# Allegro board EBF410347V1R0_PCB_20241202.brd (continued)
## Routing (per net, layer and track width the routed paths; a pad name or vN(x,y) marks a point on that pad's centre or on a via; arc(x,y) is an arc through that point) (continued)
VDD_5V: length 56.1
  TOP w0.203: C143.1 U22.6 ; U21.6 C132.1
  TOP w0.254: C143.1 17.14,51.56 16.84,51.26 16.84,47.01 17.25,46.61 C132.1 v1(17.92,47.34)
  TOP w0.381: R259.1 v1(124.08,15.52)
  BOTTOM w0.254: v1(11.18,54.81) 11.18,60.15 10.87,60.45 7.95,60.45 7.68,60.72 7.68,62.28 R1.2 C2.2
  BOTTOM w0.381: R84.1 26.92,23.98 27.36,24.41 v1(29.71,24.41) ; R169.1 9.26,66.22 9.66,65.83 v1(10.51,65.83) ; R132.1 v1(123.97,49.15) ; v1(122.55,31.01) C158.1 122.55,28.07 122.29,27.81 U18.3 ; R170.1 9.92,59.56 10.18,59.31 v1(10.18,54.81) ; v1(125.48,42.53) 125.05,42.95 122.89,42.95 122.55,42.61 C161.1 122.55,38.86 122.29,38.61 U19.3 ; R21.1 24.68,40.38 v1(24.68,41.43)
  vias: v1(10.18,53.81) v1(10.18,52.81) v1(10.36,37.79) v1(10.36,36.79) v1(10.36,26.29) v1(10.36,25.29) v1(11.18,53.81) v1(11.18,52.81) v1(11.34,20.32) v1(12.34,20.32) v1(16.51,42.16) v1(16.51,40.97) v1(125.08,15.52)
VDD_LCD_3V3: length 18.9
  TOP w0.254: v1(15.53,23) 15.48,23.05 U14.1 ; v1(78.71,19.42) 78.17,18.89 74.69,18.89 v1(74.15,19.42) 73.62,18.89 68.65,18.89 68.28,18.52 68.28,16.74 67.77,16.23 v1(67.03,16.23)
  BOTTOM w0.254: R176.1 v1(78.71,19.42) ; C140.1 C139.1 15.51,22.99 v1(15.53,23) ; R177.1 v1(74.15,19.42)
  vias: v1(15.53,24) v1(66.03,16.23)
VDD_LCD_5V:
  vias: v1(17.72,13.27) v1(18.72,13.27) v1(67.03,15.23) v1(67.03,14.23)
VDD_LVDS: length 24.9
  TOP w0.254: Y2.4 v1(18.16,32.98)
  TOP w0.381: U27.5 v1(12.99,26.61) ; v1(16.54,27.55) 16.76,27.33 16.76,22.45 17.52,21.7
  ART03 w0.254: v1(18.16,32.98) 17.26,32.08 13.31,32.08 12.8,31.57 12.8,29.36 12.52,29.08 12.52,27.08 v1(12.99,26.61)
  ART04 w0.381: v1(12.99,26.61) 13.67,25.93 16.26,25.93 16.54,26.22 v1(16.54,27.55)
VDDIO_LVDS: length 17.2
  TOP w0.203: U10.10 29.44,27.91
  TOP w0.254: v1(32.89,30.22) 32.89,32.35 32.53,32.71 31.71,32.71 C113.1 ; C93.1 v1(30.4,27.05) 30.4,27.64 30.13,27.91 29.44,27.91
  TOP w0.381: v1(29.4,30.1) 30.42,31.11 C94.1 C113.1 30.82,32.43 L13.2
  BOTTOM w0.254: C93.1 v1(30.4,27.05) 29.67,27.05 29.41,27.31 C91.1 C112.1 29.41,30.1 v1(29.4,30.1) ; R73.1 v1(32.89,30.22)
BAT_RTC: length 10.1
  TOP w0.381: J23.1 122.89,61.11 122.48,60.7 D44.2 117.93,60.03 C116.1 v1(118.7,59.31)
  BOTTOM w0.381: v1(118.7,59.31) 118.76,59.37 D43.1
BT_HOST_WAKE: length 52.3
  TOP w0.173: R158.1 v1(108.54,72.62) ; J3.46 82.34,63.9 82.02,63.58 82.02,61.82 81,60.81 v1(77.42,60.81)
  ART03 w0.16: v1(108.54,72.62) 107.83,73.33 99.46,73.33 98.93,72.81 98.93,68.55 98.53,68.15 93.2,68.15 91.52,66.47 77.49,66.47 77.17,66.15 77.17,61.06 v1(77.42,60.81)
BT_REG_ON: length 44.9
  TOP w0.173: v1(85.84,63.9) 85.8,63.93 85.8,64.59 85.59,64.8 J3.47 ; v1(117.7,55.89) 118.7,55.89 119.19,56.39 119.19,57.55 118.82,57.91 R155.2
  BOTTOM w0.173: v1(85.84,63.9) 86.03,63.71 86.03,60.67 86.38,60.32 96.89,60.32 97.65,59.56 99.29,59.56 99.85,59 99.85,57.09 100.19,56.74 116.85,56.74 v1(117.7,55.89)
BT_UART_CTS: length 2.4
  TOP w0.173: R154.2 116.67,65.91 U16.44
BT_UART_RTS: length 3.3
  TOP w0.173: U16.41 116.84,63.21 R150.2 R129.1
BT_UART_RXD: length 2.3
  TOP w0.173: R153.2 116.78,65 U16.43
BT_UART_TXD: length 2.3
  TOP w0.173: U16.42 116.9,64.11 R152.2
BT_WAKE: length 55.3
  TOP w0.173: v1(77.42,59.81) 78.01,60.4 81.1,60.4 82.7,62 82.7,62.71 82.99,63 J3.45
  TOP w0.254: R156.1 v1(109.55,72.62)
  ART03 w0.254: v1(109.55,72.62) 108.38,73.79 99.17,73.79 98.45,73.07 98.45,68.92 98.13,68.6 92.61,68.6 91.16,67.16 77.01,67.16 76.5,66.65 76.5,60.72 v1(77.42,59.81)
CAM0_NRST: length 50.6
  TOP w0.173: v1(30.51,39.6) 29.69,40.43 U17.5
  ART03 w0.16: v1(30.51,39.6) 29.91,38.99 24.17,38.99 23.85,38.67 23.85,36.82 23.38,36.35 16.48,36.35 15.28,35.14 12.06,35.14 11.79,34.87 11.79,29.18 11.43,28.83 11.43,21.08 5.97,15.62 5.97,12.95 v1(5.37,12.36)
  BOTTOM w0.173: J24.22 v1(5.37,12.36)
CAM0_PWDN: length 47.5
  TOP w0.173: v1(29.51,39.6) 29.34,39.78 U17.4
  ART03 w0.16: v1(5.37,14.86) 5.37,15.62 10.97,21.22 10.97,29.01 10.69,29.29 10.69,30.1 11.33,30.73 11.33,35.03 11.86,35.56 14.99,35.56 16.1,36.68 23.02,36.68 23.34,37 23.34,39.28 23.66,39.6 v1(29.51,39.6)
  BOTTOM w0.173: v1(5.37,14.86) 5.38,14.87 5.38,15.57 5.67,15.86 J24.15
CAM1_NRST: length 39.4
  TOP w0.173: v1(25.43,44.96) 25.43,43.93 26.19,43.18 26.19,42.06 26.52,41.73 U17.7
  ART03 w0.16: v1(5.38,29.75) 6.23,30.6 6.23,36.87 7.24,37.88 7.24,42.52 7.56,42.84 19.4,42.84 21.01,44.45 24.93,44.45 v1(25.43,44.96)
  BOTTOM w0.173: J28.22 v1(5.38,29.75)
CAM1_PWDN: length 36.9
  TOP w0.173: U17.6 25.54,41.08 25.19,41.42 25.19,43.36 24.43,44.12 v1(24.43,44.96)
  ART03 w0.16: v1(24.43,44.96) 21.03,44.96 19.23,43.15 7.25,43.15 6.93,42.83 6.93,38.01 5.92,37 5.92,33.79 v1(5.38,33.25)
  BOTTOM w0.173: J28.15 v1(5.38,33.25)
CAM2_NRST: length 34.2
  TOP w0.173: U17.9 29.18,43.03 29.46,43.31 v1(29.46,44.5)
  BOTTOM w0.173: J29.22 7.47,47.15 7.77,47.45 7.77,50.32 8.21,50.75 15.5,50.75 16.21,51.46 18.61,51.46 19.76,50.32 19.76,48.36 21.01,47.12 29.11,47.12 29.46,46.76 v1(29.46,44.5)
CAM2_PWDN: length 34.3
  TOP w0.173: v1(30.46,44.5) 30.46,42.71 30.13,42.38 U17.8
  BOTTOM w0.173: J29.15 7.59,50.65 8.03,51.08 15.27,51.08 15.98,51.79 18.89,51.79 20.24,50.43 20.24,48.39 21.01,47.62 30.12,47.62 30.46,47.28 v1(30.46,44.5)
CAM3_NRST: length 49.4
  TOP w0.173: v1(24.68,51.69) 24.68,51.21 24.91,50.98 25.98,50.98 26.39,50.57 26.39,44.6 26.67,44.33 U17.11
  ART03 w0.16: v1(24.68,51.69) 24.2,52.17 24.2,57.46 23.88,57.78 6.71,57.78 6.36,58.13 6.36,62.32 5.93,62.74 1.82,62.74 v1(1.78,62.78)
  BOTTOM w0.173: J30.22 5.56,64.51 5.36,64.31 5.36,63.65 5.05,63.35 2.35,63.35 v1(1.78,62.78)
CAM3_PWDN: length 54.6
  TOP w0.173: v1(23.68,51.69) 23.67,51.68 23.67,50.85 23.95,50.57 25.64,50.57 25.98,50.22 25.98,44.14 26.45,43.68 U17.10
  ART03 w0.16: v1(1.78,63.78) 1.27,63.27 1.27,62.56 1.56,62.27 5.65,62.27 5.97,61.94 5.97,57.85 6.42,57.4 23.36,57.4 23.72,57.04 23.72,51.73 v1(23.68,51.69)
  BOTTOM w0.173: v1(1.78,63.78) 4.53,63.78 4.9,64.15 4.9,67.67 5.25,68.01 J30.15
CAN0_H: length 3.2
  BOTTOM w0.173: R238.1 R237.1 127.63,26.54 U18.7
CAN0_L: length 3.2
  BOTTOM w0.173: R251.1 R237.2 127.63,27.81 U18.6
CAN0_RX_M2: length 1.2
  BOTTOM w0.173: R243.2 R240.1
CAN0_TX_M2: length 1.2
  BOTTOM w0.173: R241.2 R239.1
CAN1_H: length 3.2
  BOTTOM w0.173: U19.7 127.63,37.34 R247.1 R252.1
CAN1_L: length 3.2
  BOTTOM w0.173: R258.1 R247.2 127.63,38.61 U19.6
CAN1_RX_M1: length 1
  BOTTOM w0.173: R257.2 R246.1
CAN1_TX_M1: length 1
  BOTTOM w0.173: R245.1 R248.2
CLK_32K_IN: length 93.9
  TOP w0.173: v1(82.04,57.48) 81.99,57.43 81.99,24 82.09,23.9 J3.200
  ART03 w0.16: v1(82.04,57.48) 83.26,57.48 83.57,57.78 83.57,59.69 83.93,60.06 93.79,60.06 95.33,61.59 100.15,61.59 100.56,62 100.56,64.41 100.84,64.69 105.66,64.69 106.07,64.29 106.07,61.95 106.4,61.62 120.21,61.62 v1(120.7,62.1)
  BOTTOM w0.173: R135.2 118.48,65.63 118.49,65.64 120.18,65.64 120.7,65.13 v1(120.7,62.1)
DGB_RX: length 5.5
  TOP w0.173: J15.2 4.1,82.57 D30.1 4.1,79.02 R70.1
DGB_TX: length 5.6
  TOP w0.173: R69.1 8.29,79.02 D31.1 8.29,82.36 J15.1
ETH_PHY_LED1: length 76.5
  TOP w0.173: v1(50.39,40.67) 49.69,39.97 J3.164
  ART03 w0.16: J10.10 26.59,71.97 26.91,71.65 36.83,71.65 38.48,70 47.73,70 48.13,69.59 48.13,59.63 50.29,57.47 50.29,40.77 v1(50.39,40.67)
ETH_PHY_LED2: length 66.4
  TOP w0.173: J3.165 50.59,39.41 51.39,40.21 v1(51.39,40.67)
  ART03 w0.16: J10.12 38.42,70.78 38.84,70.36 48.22,70.36 48.54,70.04 48.54,59.92 50.77,57.68 50.77,41.29 v1(51.39,40.67)
ETH_PHY_MDIN0: length 54.6
  TOP w0.114: J3.153 39.79,22.35 39.46,22.68 39.46,25.63 39.79,25.96 42.09,25.96 42.6,26.47 42.6,51.08 42.82,51.31 v1(42.98,51.31)
  BOTTOM w0.114: v1(42.98,51.31) 42.66,51.63 42.66,52.42 42.18,52.9 39.2,52.9 38.5,52.2 34.29,52.2 34.06,52.42 34.06,56.11 33.71,56.46 29.34,56.46 28.95,56.85 28.95,58.47 C55.1
ETH_PHY_MDIN1: length 51.6
  TOP w0.114: v1(44.71,52.98) 44.39,52.66 44.39,25.21 44.06,24.88 42.39,24.88 42.16,24.65 42.16,22.68 42.49,22.35 J3.156
  BOTTOM w0.114: v1(44.71,52.98) 44.39,53.31 44.39,53.99 43.98,54.39 39.4,54.39 38.39,53.39 35.7,53.39 35.56,53.53 35.56,57.02 35.2,57.38 33.6,57.38 33.39,57.59 33.39,58.47 C57.1
ETH_PHY_MDIN2: length 46.7
  TOP w0.114: J3.159 45.19,22.35 44.86,22.68 44.86,23.51 45.01,23.66 45.83,23.66 46.09,23.91 46.09,54.33 v1(46.41,54.66)
  BOTTOM w0.114: v1(46.41,54.66) 46.08,55 46.08,55.61 45.71,55.98 38.3,55.98 37.84,56.44 37.84,58.47 C59.1
ETH_PHY_MDIN3: length 42.9
  TOP w0.114: v1(42.61,57.48) 42.28,57.15 42.28,56.44 42.51,56.22 47.19,56.22 47.56,55.85 47.56,22.68 47.89,22.35 J3.162
  BOTTOM w0.114: C61.1 42.28,58.47 42.28,57.8 v1(42.61,57.48)
ETH_PHY_MDIP0: length 54.4
  TOP w0.114: J3.152 38.89,22.35 39.22,22.68 39.22,25.73 39.69,26.2 41.99,26.2 42.35,26.57 42.35,51.05 v1(42.09,51.31)
  BOTTOM w0.114: C54.1 28.71,58.47 28.71,56.75 29.24,56.22 33.61,56.22 33.82,56.01 33.82,52.32 34.19,51.95 38.6,51.95 39.3,52.66 42.08,52.66 42.42,52.32 42.42,51.63 v1(42.09,51.31)
ETH_PHY_MDIP1: length 51.8
  TOP w0.114: v1(43.82,52.98) 43.99,52.98 44.15,52.83 44.15,25.31 43.96,25.12 42.29,25.12 41.92,24.75 41.92,22.68 41.59,22.35 J3.155
  BOTTOM w0.114: v1(43.82,52.98) 43.99,52.98 44.15,53.14 44.15,53.89 43.88,54.15 39.5,54.15 38.49,53.15 35.6,53.15 35.32,53.43 35.32,56.92 35.1,57.14 33.5,57.14 33.15,57.49 33.15,58.47 C56.1
ETH_PHY_MDIP2: length 46.9
  TOP w0.114: J3.158 44.29,22.35 44.62,22.68 44.62,23.61 44.91,23.9 45.73,23.9 45.85,24.01 45.85,54.53 45.72,54.66 v1(45.52,54.66)
  BOTTOM w0.114: v1(45.52,54.66) 45.62,54.66 45.83,54.88 45.83,55.51 45.61,55.74 38.2,55.74 37.6,56.34 37.6,58.47 C58.1
ETH_PHY_MDIP3: length 42.9
  TOP w0.114: v1(41.72,57.48) 42.04,57.15 42.04,56.34 42.41,55.98 47.09,55.98 47.32,55.75 47.32,22.68 46.99,22.35 J3.161
  BOTTOM w0.114: C60.1 42.04,58.47 42.04,57.8 v1(41.72,57.48)
EXT_PWR_EN: length 115
  TOP w0.173: J3.13 v1(85.46,34.2)
  ART03 w0.16: v1(41.63,40.27) 43.9,40.27 44.22,40.59 44.22,67.24 43.9,67.56 31.36,67.56 31.04,67.24 31.04,62.64 30.66,62.25 16.72,62.25 v1(16.15,62.83)
  BOTTOM w0.173: R3.2 17.12,61.86 v1(16.15,62.83) ; v1(41.63,40.27) 45.98,40.27 46.33,39.92 46.33,34.51 46.63,34.21 85.45,34.21 v1(85.46,34.2)
FAN_CTRL: length 60.9
  TOP w0.173: v1(117.91,46.92) 124.55,46.92 124.97,47.34 v1(124.97,49.15) ; J3.40 85.35,58.5 85.7,58.85 85.7,59.54 86.53,60.36 v1(86.53,61.21)
  BOTTOM w0.173: v1(117.91,46.92) 119.06,46.92 119.41,47.27 119.41,54.89 117.14,57.16 100.65,57.16 100.3,57.5 100.3,60.46 99.81,60.96 93.42,60.96 92.93,61.46 86.77,61.46 v1(86.53,61.21) ; R137.1 v1(124.97,49.15)
GM8775C_DA0N: length 6
  TOP w0.114: U10.15 27.15,30.16 27.28,30.29 27.28,31.26 27.56,31.55 28.19,31.55 28.45,31.29 28.45,30.99 28.57,30.86 28.96,30.86 29.08,30.98 29.08,32.06 28.97,32.18 28.82,32.18 28.7,32.29 R89.2
GM8775C_DA0P: length 6
  TOP w0.114: R86.2 29.7,32.29 29.59,32.18 29.44,32.18 29.32,32.06 29.32,30.88 29.06,30.62 28.48,30.62 28.21,30.89 28.21,31.19 28.09,31.3 27.66,31.3 27.52,31.16 27.52,30.29 27.65,30.16 U10.14
GM8775C_DA1N: length 3.7
  TOP w0.114: R93.2 27.08,32.24 27.08,32.06 26.9,31.89 26.56,31.89 26.28,31.61 26.28,30.29 26.15,30.16 U10.17
GM8775C_DA1P: length 3.8
  TOP w0.114: R90.2 27.32,32.23 27.32,31.96 27,31.65 26.66,31.65 26.52,31.51 26.52,30.29 26.65,30.16 U10.16
GM8775C_DA2N: length 4.2
  TOP w0.114: R97.2 22.7,32.29 22.82,32.18 22.97,32.18 23.08,32.06 23.08,31.8 23.44,31.44 24.08,31.44 24.28,31.25 24.28,30.29 24.15,30.16 U10.21
GM8775C_DA2P: length 4.2
  TOP w0.114: U10.20 24.65,30.16 24.52,30.29 24.52,31.35 24.18,31.69 23.54,31.69 23.32,31.9 23.32,32.06 23.44,32.18 23.59,32.18 23.7,32.29 R94.2
GM8775C_DA3N: length 4.9
  TOP w0.114: R102.2 20.7,32.29 20.82,32.18 20.97,32.18 21.08,32.06 21.08,31.59 21.62,31.05 22.75,31.05 23.28,30.52 23.28,30.29 23.15,30.16 U10.23
GM8775C_DA3P: length 4.9
  TOP w0.114: R99.2 21.7,32.29 21.59,32.18 21.44,32.18 21.32,32.06 21.32,31.69 21.72,31.29 22.85,31.29 23.52,30.62 23.52,30.29 23.65,30.16 U10.22
GM8775C_DACN: length 3.3
  TOP w0.114: U10.19 25.15,30.16 25.28,30.29 25.28,31.38 25.08,31.57 25.08,32.24 R107.2
GM8775C_DACP: length 3.3
  TOP w0.114: U10.18 25.65,30.16 25.52,30.29 25.52,31.48 25.32,31.67 25.32,32.24 R104.2
GM8775C_RSTN: length 53.3
  TOP w0.173: C95.1 v1(30.4,30.1) 29.9,29.59 29.9,29.11 29.7,28.91 U10.12
  BOTTOM w0.173: v1(30.4,30.1) 30.53,30.22 R73.2 31.73,29.62 33.56,29.62 33.91,29.27 33.91,27.45 34.25,27.1 69.12,27.1 69.47,26.76 69.47,19.18 R187.2
GPIO0_C0: length 59.8
  TOP w0.173: v1(87.19,59.32) 87.18,59.31 87.18,58.1 85.78,56.7 J3.38
  BOTTOM w0.173: R248.1 118.74,36.43 R253.1 116.84,36.33 116.84,40.64 116.41,41.07 116.41,47.55 117.91,49.05 117.91,53.49 115.45,55.96 99.54,55.96 99.01,56.49 99.01,57.1 98.7,57.4 96.57,57.4 96.22,57.76 96.22,58.98 95.87,59.32 v1(87.19,59.32)
GPIO0_C1: length 56.3
  TOP w0.173: J3.39 85.82,57.6 86.19,57.97 v1(86.19,59.32)
  BOTTOM w0.173: v1(86.19,59.32) 86.69,59.82 96.38,59.82 96.73,59.47 96.73,58.75 97.06,58.42 98.93,58.42 99.39,57.96 99.39,56.77 99.85,56.31 116.56,56.31 118.4,54.48 118.4,47.91 118.08,47.6 117.19,47.6 116.84,47.25 116.84,43.92 117.74,43.02 R255.1 117.74,40.5 R257.1
GPIO0_C6: length 84.8
  TOP w0.173: J3.43 82.66,61.2 v1(82.65,61.19)
  BOTTOM w0.173: R242.1 R241.1 124.17,22.07 119.16,22.07 118.75,22.48 118.75,31.09 118.31,31.52 115.19,31.52 114.25,32.46 114.25,40.11 115.6,41.46 115.6,47.88 116.41,48.69 116.41,51.46 115.49,52.37 110.41,52.37 109.25,53.54 105.66,53.54 104.55,52.42 100.13,52.42 99.49,53.06 96.39,53.06 95.73,53.72 92.22,53.72 91.89,54.05 91.89,54.86 91.54,55.21 83.98,55.21 82.93,56.26 82.93,59.03 82.09,59.87 82.09,60.63 v1(82.65,61.19)
GPIO0_C7: length 72.6
  TOP w0.173: J3.44 85.19,62.1 85.53,61.77 v1(85.53,61.21)
  BOTTOM w0.173: v1(85.53,61.21) 85.53,58.49 85.87,58.14 95.36,58.14 95.71,57.79 95.71,56.68 96.06,56.34 98.5,56.34 99.31,55.52 115.24,55.52 117.53,53.24 117.53,49.22 116.08,47.78 116.08,41.25 114.71,39.88 114.71,33.02 115.17,32.56 123.9,32.56 R243.1 R244.1
GPIO0C0: length 10.5
  BOTTOM w0.173: R253.2 118.74,34.3 119,34.03 127.13,34.03 127.75,33.41 R254.1
GPIO0C1: length 13.4
  BOTTOM w0.173: R255.2 118.36,40.88 118.36,43.18 118.87,43.69 127.38,43.69 127.76,43.31 R256.1
GPIO0C6: length 1
  BOTTOM w0.173: R242.2 126.75,22.61 R249.1
GPIO0C7: length 1
  BOTTOM w0.173: R250.1 126.75,31.74 R244.2
HP_BUTTON_DET: length 109.7
  TOP w0.173: v1(86.5,55.7) 86.1,55.29 86.1,52.5 85.79,52.2 J3.33
  ART03 w0.16: v1(86.5,55.7) 76.24,55.7 75.92,56.02 75.92,62.31 75.55,62.68 75.55,67.47 75.87,67.79 85.7,67.79 86.39,68.48 86.39,71.38 86.71,71.7 94.4,71.7 94.81,72.11 94.81,77.01 96.09,78.29 96.09,81.33 95.38,82.03 76.65,82.03 74.88,80.26 72.14,80.26 71.01,81.39 v1(55.43,81.39)
  BOTTOM w0.173: C40.1 R29.1 ; C40.1 53.25,78.82 54.59,78.82 54.92,79.15 54.92,80.88 v1(55.43,81.39) ; C40.1 R26.2
HP_PLUG_IN_DET: length 86.7
  TOP w0.173: J3.196 v1(78.49,22.71)
  ART03 w0.16: v1(52.45,82.41) 52.45,81.14 52.7,80.88 66.88,80.88 67.49,80.27 67.49,69.7 67.81,69.38 71.65,69.38 72.01,69.02 72.01,23.03 72.33,22.71 v1(78.49,22.71)
  BOTTOM w0.173: R36.2 v1(52.45,82.41)
HP_SNS: length 69.2
  TOP w0.254: J3.22 82.86,42.3 v1(82.86,42.3)
  ART03 w0.254: v1(52.39,41.94) 52.39,58 49.83,60.55 v1(49.83,72.61)
  BOTTOM w0.254: v1(82.86,42.3) 82.59,42.57 53.02,42.57 v1(52.39,41.94) ; v1(49.83,72.61) 49.29,73.15 47.37,73.15 46.61,72.39 45.84,72.39 R38.2
HPL_OUT: length 178.1
  TOP w0.254: J3.21 82.96,41.4 v1(82.86,41.3)
  ART03 w0.254: v1(50.83,72.61) 50.24,72.02 50.24,60.81 52.8,58.25 52.8,42.54 v1(53.39,41.94)
  ART04 w0.254: v1(50.83,72.61) 50.22,73.23 48.51,73.23 48.13,72.85 48.13,70.08 47.75,69.7 18.29,69.7 17.78,70.2 17.78,72.97 17.12,73.63 6.4,73.63 5.89,73.13 5.89,44.17 6.65,43.41 6.65,27.94 7.16,27.43 14.73,27.43 15.84,28.54 v1(15.84,29.84)
  BOTTOM w0.254: C34.1 15.49,30.19 v1(15.84,29.84) ; v1(82.86,41.3) 82,42.16 53.61,42.16 v1(53.39,41.94) ; R33.2 46.79,73.58 49.86,73.58 v1(50.83,72.61)
HPR_OUT: length 141.5
  TOP w0.254: J3.23 82.96,43.2 v1(82.86,43.3)
  ART03 w0.254: v1(51.39,41.94) 51.98,42.54 51.98,57.77 49.43,60.33 49.43,72.02 v1(48.83,72.61)
  ART04 w0.254: v1(9.18,55.81) 7.04,55.81 6.35,56.5 6.35,72.62 6.86,73.13 16.79,73.13 17.3,72.62 17.3,69.62 17.81,69.11 48.33,69.11 48.83,69.62 v1(48.83,72.61)
  BOTTOM w0.254: C46.1 9.18,54.06 v1(9.18,55.81) ; v1(51.39,41.94) 52.43,42.98 82.54,42.98 v1(82.86,43.3) ; R34.2 45.25,71.96 46.86,71.96 47.52,72.61 v1(48.83,72.61)
I2C0_SCL: length 203.1
  TOP w0.173: U17.22 26.03,39.13 26.48,38.68 v1(26.48,36.71) ; J3.194 76.69,23.91 77.03,24.26 80.6,24.26 80.95,24.6 v1(80.95,57.48)
  ART03 w0.16: v1(112.92,62.68) 112.73,62.48 107.08,62.48 106.73,62.83 106.73,64.86 106.41,65.18 100.1,65.18 99.67,64.74 99.67,63.04 99.24,62.61 95.4,62.61 93.33,60.54 91.24,60.54 90.98,60.8 83.38,60.8 83.08,60.5 83.08,58.52 82.66,58.09 81.56,58.09 v1(80.95,57.48)
  BOTTOM w0.173: v1(112.92,62.68) 113.2,62.41 U15.6 ; v1(80.95,57.48) 80.95,56.18 80.59,55.83 50.27,55.83 49.33,54.89 49.33,46.81 49.15,46.63 39.8,46.63 39.01,45.85 33.1,45.85 32.56,45.31 32.56,40.74 30.84,39.01 28.82,39.01 28.19,38.39 28.19,37.06 27.85,36.71 v1(26.48,36.71) 25.95,37.24 25.3,37.24 24.33,36.27 23.44,36.27 23.21,36.03 23.21,35.11 23.04,34.94 16.44,34.94 15.88,35.51 9.03,35.51 8.69,35.16 8.69,29.66 5,25.98 1.91,25.98 1.47,25.54 1.47,21.2 1.65,21.03 2.84,21.03 3.52,20.36 J24.6
I2C0_SDA: length 205.6
  TOP w0.173: J3.193 75.79,24.42 76.13,24.76 79.97,24.76 80,24.81 80.37,25.18 80.37,58.03 v1(80.95,58.61) ; U17.23 25.13,38.48 25.48,38.13 v1(25.48,36.71)
  ART03 w0.16: v1(80.95,58.61) 80.26,59.29 80.26,63.1 80.58,63.42 92.13,63.42 93.98,65.28 95.63,65.28 96.77,66.42 106.89,66.42 107.21,66.1 107.21,64.18 107.72,63.68 v1(112.92,63.68)
  BOTTOM w0.173: U15.5 113.24,63.06 112.92,63.38 v1(112.92,63.68) ; J24.5 3.52,20.86 2.95,21.44 2.06,21.44 1.87,21.63 1.87,25.31 2.22,25.65 5.33,25.65 9.14,29.46 9.14,34.84 9.49,35.18 15.69,35.18 16.26,34.61 24.04,34.61 24.21,34.79 24.21,35.77 24.38,35.94 24.7,35.94 v1(25.48,36.71) 26.12,36.07 28.36,36.07 28.7,36.41 28.7,38.2 29.18,38.68 31.09,38.68 32.97,40.56 32.97,44.88 33.48,45.39 39.07,45.39 39.83,46.15 49.67,46.15 49.89,46.37 49.89,54.76 50.47,55.35 80.95,55.35 81.44,55.83 81.44,58.11 v1(80.95,58.61)
I2C1_SCL_M1: length 182.1
  TOP w0.173: v1(66.93,18.42) 65.53,17.02 65.53,12.24 65.16,11.86 63.17,11.86 v1(62.68,12.36) 62.06,12.36 60.55,13.87 48.83,13.87 48.49,14.22 48.49,18.45 48.14,18.79 32.47,18.79 32.12,19.14 R74.1 32.89,23.76 v1(32.89,24) ; J3.57 76.69,65.63 76.34,65.28 v1(69.39,65.28) ; v1(4.36,38.75) 4.36,35.76 3.89,35.28 3.89,27.91 4.27,27.53 4.27,23.21 3.89,22.83 v1(3.89,22.36) 3.89,18.64 4.23,18.29 J19.4
  ART03 w0.16: v1(69.39,65.28) 69.39,18.74 69.07,18.42 v1(66.93,18.42)
  BOTTOM w0.173: v1(69.39,65.28) 69.34,65.24 R174.2 ; J18.9 62.18,12.86 v1(62.68,12.36) ; v1(4.36,38.75) 4.36,38.1 4.71,37.75 J28.6 ; v1(3.89,22.36) 4.39,21.85 5.34,21.85 5.66,22.17 5.66,24.71 9.96,29.01 13.51,29.01 13.87,28.65 18.85,28.65 19.2,29.01 26.67,29.01 27.13,28.54 27.13,26.31 27.48,25.96 30.07,25.96 30.48,25.55 30.48,24.26 30.73,24 v1(32.89,24)
I2C1_SDA_M1: length 180
  TOP w0.173: R75.1 32.89,24.77 v1(32.89,25) 33.39,24.51 33.39,19.6 33.73,19.25 48.55,19.25 48.9,18.91 48.9,14.54 49.24,14.2 60.78,14.2 62.13,12.85 63.19,12.85 v1(63.68,12.36) 64.83,12.36 65.18,12.7 65.18,17.67 v1(66.93,19.42) ; v1(4.36,39.75) 4.77,39.75 5.16,39.37 5.16,35.53 4.62,35 4.62,28.37 4.89,28.11 v1(4.89,22.36) 4.89,20.7 5.3,20.29 J19.5 ; J3.58 75.79,66.13 75.44,65.79 68.88,65.79 v1(68.37,65.28)
  ART03 w0.16: v1(66.93,19.42) 68.64,19.42 68.96,19.74 68.96,64.69 v1(68.37,65.28)
  BOTTOM w0.173: v1(63.68,12.36) 63.18,11.86 62.43,11.86 61.68,12.62 J18.10 ; J28.5 5.19,38.25 4.89,38.55 4.89,39.22 v1(4.36,39.75) ; v1(32.89,25) 31.13,25 30.86,25.27 30.86,25.73 30.3,26.29 27.8,26.29 27.46,26.63 27.46,28.95 27.05,29.36 19.02,29.36 18.67,29.01 14.07,29.01 13.74,29.34 9.83,29.34 5.34,24.85 5.34,22.81 v1(4.89,22.36) ; v1(68.37,65.28) 68.33,65.24 R175.2
I2C2_SCL_M1: length 102.3
  TOP w0.173: v1(67.35,64.27) 78.14,64.27 78.49,64.61 J3.55
  ART03 w0.16: v1(22.68,51.69) 23.24,52.24 23.24,56.29 22.92,56.61 10.74,56.61 8.94,54.81 v1(8.18,54.81)
  BOTTOM w0.173: R189.2 67.31,64.22 v1(67.35,64.27) 66.86,64.76 47.74,64.76 47.4,64.41 47.4,49.34 47.05,49 23.11,49 22.68,49.42 v1(22.68,51.69) ; v1(8.18,54.81) 7.85,55.15 J29.6
I2C2_SDA_M1: length 103.7
  TOP w0.173: v1(66.34,64.27) 66.84,64.77 77.24,64.77 77.59,65.11 J3.56
  ART03 w0.16: v1(21.68,51.69) 22.2,52.2 22.2,56.03 21.95,56.29 10.92,56.29 8.97,54.33 6.68,54.33 v1(5.36,55.65)
  BOTTOM w0.173: J29.5 v1(5.36,55.65) ; R190.2 66.29,64.22 v1(66.34,64.27) 48.17,64.27 47.83,63.92 47.83,48.96 47.48,48.61 22.12,48.61 21.68,49.05 v1(21.68,51.69)
I2C5_SCL_M1: length 103.5
  TOP w0.173: v1(40.68,37.92) 40.89,37.71 40.89,27.86 40.26,27.23 37.9,27.23 37.47,26.8 37.47,25.37 37.29,25.2 v1(37.29,25.2) J3.148
  ART03 w0.16: v1(4.43,74.51) 4.93,74.01 16.82,74.01 17.14,73.69 17.14,70.81 17.75,70.2 35.71,70.2 37.47,68.45 44.66,68.45 45.09,68.03 45.09,54.02 45.52,53.59 45.52,37.78 45.13,37.39 41.21,37.39 v1(40.68,37.92)
  BOTTOM w0.173: v1(4.43,74.51) 3.98,74.51 3.78,74.32 3.78,73.23 3.99,73.02 4.65,73.02 5.16,72.51 J30.6 ; R191.2 37.26,25.17 v1(37.29,25.2)
I2C5_SDA_M1: length 99
  TOP w0.173: v1(41.63,37.92) 41.22,37.51 41.22,27.73 40.39,26.9 38.03,26.9 37.8,26.67 37.8,24.72 37.29,24.21 v1(37.29,24.2) 37.19,24.3 J3.149
  ART03 w0.16: v1(4.43,73.51) 16.44,73.51 16.76,73.19 16.76,70.69 17.6,69.85 35.46,69.85 37.21,68.1 44.21,68.1 44.63,67.67 44.63,53.75 45.21,53.16 45.21,38.25 44.88,37.92 v1(41.63,37.92)
  BOTTOM w0.173: J30.5 5.19,73.01 4.69,73.51 v1(4.43,73.51) ; R192.2 37.25,24.15 v1(37.29,24.2)
I2S2_LRCK_M0: length 73.2
  TOP w0.173: J3.182 65.89,28.74 66.23,29.08 75.18,29.08 75.52,29.43 75.52,49.62 v1(76.02,50.11) ; R157.2 v1(108.79,47.75)
  ART03 w0.16: v1(76.02,50.11) 76.63,49.5 76.63,48.6 76.95,48.28 108.26,48.28 v1(108.79,47.75)
I2S2_SCLK_M0: length 69.1
  TOP w0.173: R160.2 v1(107.52,47.75) ; J3.184 67.69,28.1 68.03,28.45 75.7,28.45 76.04,28.79 76.04,49.09 v1(76.02,49.11)
  ART03 w0.16: v1(107.52,47.75) 76.35,47.75 76.02,48.08 v1(76.02,49.11)
I2S2_SDI_M0: length 68.6
  TOP w0.173: v1(77.17,50.11) 76.66,49.61 76.66,28.16 76.31,27.81 68.93,27.81 68.59,27.47 J3.185 ; R161.2 v1(107.52,50.42)
  ART03 w0.16: v1(77.17,50.11) 78.03,49.25 106.35,49.25 v1(107.52,50.42)
I2S2_SDO_M0: length 68.2
  TOP w0.173: R159.2 v1(108.79,50.42) ; J3.186 69.49,26.96 69.83,27.3 76.82,27.3 77.17,27.65 v1(77.17,49.11)
  ART03 w0.16: v1(77.17,49.11) 77.51,48.77 107.14,48.77 v1(108.79,50.42)
IO0_C0: length 42.1
  TOP w0.173: v1(115.21,37.13) 115.79,37.72 117.34,37.72 D74.1 124.17,37.13 124.51,36.79 124.51,24.52 124.04,24.05 J22.5
  ART03 w0.16: v1(115.21,37.13) 115.69,37.62 124.71,37.62 125.09,37.24 v1(125.09,35.05)
  BOTTOM w0.173: v1(125.09,35.05) 125.48,35.44 R252.2 R254.2
IO0_C1: length 44.4
  TOP w0.173: v1(115.21,35.99) 115.74,36.53 117.39,36.53 D37.1 123.71,35.99 124.06,35.65 124.06,26.39 123.71,26.05 J22.4
  ART03 w0.16: v1(127.01,41.54) 127.01,34.73 126.75,34.47 124.66,34.47 124.38,34.75 124.38,36.32 124.05,36.65 115.87,36.65 v1(115.21,35.99)
  BOTTOM w0.173: v1(127.01,41.54) R256.2 R258.2
IO0_C6: length 42
  TOP w0.173: J22.3 123.25,28.05 123.6,28.39 123.6,34.5 123.25,34.85 D36.1 117.34,35.43 115.79,35.43 v1(115.21,34.85)
  ART03 w0.16: v1(115.21,34.85) 115.66,35.3 122.96,35.3 124.36,33.91 127.13,33.91 127.64,33.4 127.64,25.25 127.03,24.65 v1(127.01,24.65)
  BOTTOM w0.173: R249.2 R238.2 v1(127.01,24.65)
IO0_C7: length 30.7
  TOP w0.173: J22.2 122.89,30.05 123.19,30.35 123.19,33.27 122.76,33.7 D35.1 117.39,34.24 115.74,34.24 v1(115.21,33.7)
  BOTTOM w0.173: R251.2 R250.2 128.3,31.28 128.3,32.35 128.02,32.64 124.84,32.64 123.94,33.54 118.12,33.54 117.65,33.07 115.84,33.07 v1(115.21,33.7)
LCD_BL_PWM: length 52.4
  TOP w0.173: J3.64 70.39,68.3 v1(70.35,68.27)
  ART03 w0.16: v1(70.47,19.42) 70.47,66.31 69.85,66.93 69.85,67.76 v1(70.35,68.27)
  BOTTOM w0.173: R185.1 R184.1 v1(70.47,19.42)
LCD_CPT_INT: length 82.2
  TOP w0.173: J3.60 73.99,67 73.64,66.65 67.74,66.65 v1(67.35,66.27)
  ART03 w0.16: v1(82.26,19.42) 82.26,17.45 81.94,17.13 65.67,17.13 65.28,17.53 65.28,20.99 65.6,21.31 67.65,21.31 67.97,21.63 67.97,63.02 66.85,64.13 66.85,65.78 67.33,66.27 v1(67.35,66.27)
  BOTTOM w0.173: R81.1 R178.1 v1(82.26,19.42)
LCD_CPT_RST: length 76.8
  TOP w0.173: v1(67.35,65.27) 68.31,66.22 74.54,66.22 74.89,66.57 J3.59
  ART03 w0.16: v1(67.35,65.27) 68.5,64.12 68.5,21.1 68.18,20.78 66.11,20.78 65.79,20.46 65.79,17.85 66.11,17.52 77.39,17.52 77.71,17.85 v1(77.71,19.42)
  BOTTOM w0.173: R182.1 R183.1 v1(77.71,19.42)
LCD_RST: length 61.6
  TOP w0.173: J3.63 71.29,68.45 70.6,67.76 69.85,67.76 v1(69.35,67.27)
  ART03 w0.16: v1(67.69,20.14) 66.62,20.14 66.22,19.73 66.22,18.31 66.59,17.94 69.66,17.94 69.98,18.26 69.98,66.03 69.35,66.66 v1(69.35,67.27)
  BOTTOM w0.173: R187.1 R186.1 v1(67.69,20.14)
LED_BLUE: length 22.5
  TOP w0.173: v1(77.47,10.95) 77.47,12.12 77.12,12.47 66.88,12.47 66.54,12.82 66.54,16.75 67.56,17.78 67.56,19.56 66.79,20.33 J3.183
  BOTTOM w0.173: R103.1 v1(77.47,10.95)
LED_RED: length 92.1
  TOP w0.173: U17.13 23.12,44.98 23.52,44.58 23.52,39.97 23.87,39.62 26.31,39.62 26.87,39.06 26.87,37.16 27.69,36.35 30.96,36.35 v1(31.51,36.91)
  ART03 w0.16: v1(51.64,32.56) 51.64,18.29 52.02,17.91 62.23,17.91 62.61,17.52 62.61,14.1 63.12,13.59 63.12,13.08 63.37,12.83 77.52,12.83 77.85,12.5 77.85,11.27 78.17,10.95 v1(79.38,10.95)
  BOTTOM w0.173: R98.1 v1(79.38,10.95) ; v1(51.64,32.56) 45.15,32.56 44.81,32.91 44.81,38.34 44.46,38.68 39.34,38.68 38.77,38.11 32.83,38.11 31.63,36.91 v1(31.51,36.91)
LVDS_3V3: length 17
  BOTTOM w0.381: R78.2 21.64,21.6 C97.1 C96.1 23.62,20.45 23.11,19.94 14.24,19.94 J20.5
LVDS_5V: length 13.9
  BOTTOM w0.381: C104.1 24.64,19.94 24.05,19.35 15.65,19.35 J20.3
LVDS_12V: length 22.3
  TOP w0.254: J31.2 v1(5.54,42.8)
  ART04 w0.508: J20.1 16.38,17.2 ; J20.1 15.5,18.08 ; J20.1 14.62,17.2 ; J20.1 15.5,16.32
  BOTTOM w0.508: J20.1 16.97,18.67 27.69,18.67 28.19,19.18 C98.1
  vias: v1(5.54,41.8)
LVDS_BL_EN: length 92.1
  TOP w0.173: U21.3 18.91,44.15 19.2,43.86 19.77,43.86 R213.1 20.76,43.31 21.18,43.74 v1(21.18,43.99) ; v1(79.74,68.25) 79.39,68.6 J3.54
  BOTTOM w0.173: v1(21.18,43.99) 27.57,43.99 27.91,43.65 27.91,40.48 28.26,40.13 31.01,40.13 32.16,41.27 32.16,45.88 32.5,46.23 38.84,46.23 39.73,47.12 48.3,47.12 48.64,47.46 48.64,57.2 49.02,57.58 77.96,57.58 78.31,57.93 78.31,59.77 79.74,61.2 v1(79.74,68.25)
LVDS_BL_PWM: length 86.2
  TOP w0.173: U22.3 18.91,49.11 19.2,48.82 19.64,48.82 R214.1 21.71,48.27 22.05,47.93 22.05,46.02 22.28,45.8 23.51,45.8 23.85,45.45 23.85,40.48 24.2,40.13 26.72,40.13 27.28,39.57 27.28,37.36 27.74,36.91 v1(30.51,36.91)
  BOTTOM w0.173: v1(30.51,36.91) 31.1,37.49 31.6,37.49 32.59,38.48 38.56,38.48 39.21,39.14 44.89,39.14 45.26,38.77 45.26,33.54 45.61,33.2 72.58,33.2 73,32.78 73,19.16 R185.2
LVDS_BLEN: length 18.7
  TOP w0.173: R213.2 v1(20.32,44.96) R215.2 ; J31.3 v1(6.48,44.8)
  ART03 w0.16: v1(6.48,44.8) 6.48,43.92 6.83,43.56 17.12,43.56 17.98,44.42 19.76,44.42 20.29,44.96 v1(20.32,44.96)
LVDS_BLPWM: length 24.4
  TOP w0.173: J31.4 4.71,46.8 v1(4.36,47.15) ; v1(21.18,48.89) 21.18,48.92 20.84,49.27 R214.2 R216.2
  ART03 w0.16: v1(4.36,47.15) 5.74,48.52 14.79,48.52 15.12,48.84 17.42,48.84 17.75,48.51 19.25,48.51 19.63,48.89 v1(21.18,48.89)
LVDS_CPT_INT: length 117.8
  TOP w0.173: v1(8.62,10.78) 8.62,10.28 8.27,9.93 4.72,9.93 4.09,10.57 4.09,15.95 4.43,16.29 J19.3
  ART03 w0.16: v1(19.72,12.27) 19.72,11.69 19.41,11.38 17.75,11.38 17.26,11.87 17.26,13.37 16.43,14.2 15.16,14.2 14.49,14.87 14.49,15.66 13.94,16.2 8.94,16.2 8.62,15.88 v1(8.62,10.78)
  BOTTOM w0.173: R178.2 81.08,17.96 81.08,10.11 80.67,9.7 20.12,9.7 19.72,10.1 v1(19.72,12.27) ; v1(8.62,10.78) 8.26,11.14 R80.2
LVDS_CPT_RST: length 126.7
  TOP w0.173: v1(7.62,10.78) 5.2,10.78 4.85,11.12 4.85,13.95 5.2,14.29 J19.2
  ART03 w0.16: 16.51,16.17 16.79,15.89 16.79,14.55 17.27,14.07 17.99,14.07 18.24,13.83 18.24,12.75 v1(18.72,12.27)
  ART03 w0.173: v1(7.62,10.78) 7.62,16.53 9.3,18.21 14.11,18.21 14.45,17.87 14.45,16.43 14.72,16.17 16.51,16.17
  BOTTOM w0.173: v1(18.72,12.27) 18.72,9.65 19.01,9.36 81.3,9.36 81.56,9.62 81.56,17.42 82.76,18.62 82.76,19.99 82.5,20.24 78.44,20.24 78.22,20.02 78.22,18.63 78.01,18.42 77.71,18.42 R183.2 ; R82.2 7.72,20.92 7.72,10.9 7.62,10.79 v1(7.62,10.78)
LVDS_TXA_CLKN: length 38.3
  TOP w0.114: v1(19.47,28.5) 19.8,28.17 20.47,28.17 20.86,27.78 21.27,27.78 21.4,27.91 U10.27
  ART03 w0.102: v1(19.47,28.5) 19.47,28.29 19.37,28.19 19.02,28.19 18.86,28.36 18.61,28.36 18.45,28.19 18.21,28.19 18.05,28.36 17.8,28.36 17.64,28.19 17.4,28.19 17.23,28.36 16.99,28.36 16.83,28.19 16.58,28.19 16.42,28.36 16.18,28.36 16.01,28.19 15.05,28.19 14.73,27.88 14.73,27.62 14.58,27.46 14.58,27.21 14.73,27.06 14.73,26.8 14.58,26.65 14.58,26.4 14.73,26.25 14.73,25.99 14.58,25.84 14.58,25.59 14.73,25.43 14.73,25.18 14.58,25.03 14.58,24.77 14.73,24.62 14.73,20.33 15.99,19.07 22.47,19.07 22.76,19.36 22.76,19.77 22.87,19.89 23.04,19.89 23.16,19.77 23.16,19.36 23.44,19.07 30.47,19.07 31,18.54 32.42,18.54 32.69,18.27 32.69,17.33 32.56,17.2 J17.15
LVDS_TXA_CLKP: length 38.4
  TOP w0.114: U10.28 21.4,27.41 21.27,27.54 20.76,27.54 20.37,27.93 19.8,27.93 v1(19.47,27.61)
  ART03 w0.102: J17.16 31.88,15.9 32.97,16.99 32.97,18.39 32.54,18.82 31.11,18.82 30.58,19.35 23.56,19.35 23.44,19.47 23.44,19.88 23.16,20.17 22.76,20.17 22.48,19.88 22.48,19.47 22.36,19.35 16.1,19.35 15.01,20.45 15.01,27.76 15.16,27.91 19.17,27.91 v1(19.47,27.61)
LVDS_TXA_D0N: length 38.7
  TOP w0.114: U10.33 21.4,24.91 21.27,24.78 21.06,24.78 20.8,24.53 20.8,23.74 20.57,23.51 18.79,23.51 v1(18.47,23.83)
  ART03 w0.102: J17.7 40.54,17.2 40.67,17.32 40.67,21.93 40.19,22.4 32.44,22.4 32.26,22.22 32.03,22.22 31.85,22.4 31.62,22.4 31.45,22.22 31.22,22.22 31.04,22.4 30.81,22.4 30.63,22.22 30.4,22.22 30.23,22.4 30,22.4 29.82,22.22 29.59,22.22 29.41,22.4 29.18,22.4 29.01,22.22 28.78,22.22 28.6,22.4 28.12,22.4 28,22.28 28,21.69 27.71,21.41 27.31,21.41 27.03,21.69 27.03,22.28 26.91,22.4 21.36,22.4 20.99,22.03 20.62,22.03 20.45,21.87 20.21,21.87 20.05,22.03 19.81,22.03 19.64,21.87 19.4,21.87 19.23,22.03 18.99,22.03 18.83,21.87 18.59,21.87 18.42,22.03 17.72,22.03 17.45,22.3 17.45,23.21 17.76,23.53 18.36,23.53 18.47,23.63 v1(18.47,23.83)
LVDS_TXA_D0P: length 38.7
  TOP w0.114: U10.34 21.4,24.41 21.27,24.54 21.16,24.54 21.04,24.43 21.04,23.64 20.67,23.27 18.79,23.27 v1(18.47,22.94)
  ART03 w0.102: v1(18.47,22.94) 18.16,23.25 17.88,23.25 17.73,23.1 17.73,22.42 17.83,22.31 20.88,22.31 21.25,22.68 27.03,22.68 27.31,22.4 27.31,21.81 27.43,21.69 27.6,21.69 27.72,21.81 27.72,22.4 28,22.68 40.31,22.68 40.94,22.05 40.94,16.97 39.88,15.9 J17.8
LVDS_TXA_D1N: length 38.8
  TOP w0.114: v1(19.49,25.46) 19.82,25.13 20.31,25.13 20.96,25.78 21.27,25.78 21.4,25.91 U10.31
  ART03 w0.102: J17.9 38.54,17.2 38.68,17.35 38.68,19.73 38.1,20.32 36.06,20.32 35.91,20.17 35.65,20.17 35.5,20.32 35.25,20.32 35.09,20.17 34.84,20.17 34.69,20.32 34.43,20.32 34.28,20.17 34.03,20.17 33.87,20.32 33.62,20.32 33.47,20.17 33.21,20.17 33.06,20.32 32.81,20.32 32.65,20.17 32.4,20.17 32.25,20.32 31.99,20.32 31.63,20.67 26.48,20.67 26.21,20.94 26.21,21.5 26.09,21.61 25.92,21.61 25.8,21.5 25.8,20.97 25.52,20.69 25.12,20.69 24.84,20.97 24.84,21.5 24.72,21.61 21.71,21.61 21.12,21.03 20.04,21.03 19.88,20.88 19.63,20.88 19.48,21.03 19.22,21.03 19.07,20.88 18.82,20.88 18.67,21.03 18.41,21.03 18.26,20.88 18,20.88 17.85,21.03 17.08,21.03 16.69,21.42 16.69,24.7 17.14,25.15 17.51,25.15 17.66,25.3 17.92,25.3 18.07,25.15 18.33,25.15 18.47,25.3 18.73,25.3 18.88,25.15 19.39,25.15 19.49,25.26 v1(19.49,25.46)
LVDS_TXA_D1P: length 38.7
  TOP w0.114: v1(19.49,24.57) 19.82,24.89 20.41,24.89 21.06,25.54 21.27,25.54 21.4,25.41 U10.32
  ART03 w0.102: v1(19.49,24.57) 19.19,24.87 17.25,24.87 16.97,24.59 16.97,21.54 17.2,21.31 21.01,21.31 21.59,21.89 24.84,21.89 25.12,21.61 25.12,21.09 25.24,20.97 25.41,20.97 25.53,21.09 25.53,21.61 25.81,21.89 26.21,21.89 26.49,21.61 26.49,21.06 26.59,20.95 31.75,20.95 32.11,20.6 38.22,20.6 38.96,19.85 38.96,16.99 37.88,15.9 J17.10
LVDS_TXA_D2N: length 38.5
  TOP w0.114: v1(18.47,26.81) 18.79,26.48 20.64,26.48 20.94,26.78 21.27,26.78 21.4,26.91 U10.29
  ART03 w0.102: J17.11 36.5,17.2 36.68,17.37 36.68,19.15 36.47,19.36 34.7,19.36 34.54,19.2 34.29,19.2 34.13,19.36 33.88,19.36 33.73,19.2 33.48,19.2 33.32,19.36 31.24,19.36 30.63,19.96 29.94,19.96 29.79,19.81 29.53,19.81 29.38,19.96 29.13,19.96 28.97,19.81 28.72,19.81 28.57,19.96 28.31,19.96 28.16,19.81 27.91,19.81 27.75,19.96 27.5,19.96 27.35,19.81 27.09,19.81 26.94,19.96 26.69,19.96 26.54,19.81 26.28,19.81 26.13,19.96 25.88,19.96 25.72,19.81 25.47,19.81 25.32,19.96 25.06,19.96 24.91,19.81 24.66,19.81 24.5,19.96 24.25,19.96 23.98,20.23 23.98,20.78 23.86,20.9 22.37,20.9 21.37,19.9 16.93,19.9 15.9,20.93 15.9,25.96 16.45,26.5 17.09,26.5 17.26,26.67 17.5,26.67 17.67,26.5 18.35,26.5 18.47,26.62 v1(18.47,26.81)
LVDS_TXA_D2P: length 38.3
  TOP w0.114: U10.30 21.4,26.41 21.27,26.54 21.04,26.54 20.74,26.24 18.79,26.24 v1(18.47,25.92)
  ART03 w0.102: J17.12 35.88,15.91 36.96,16.99 36.96,19.27 36.58,19.64 31.35,19.64 30.75,20.24 24.36,20.24 24.26,20.34 24.26,20.9 23.98,21.18 22.25,21.18 21.25,20.18 17.04,20.18 16.18,21.04 16.18,25.84 16.56,26.22 18.16,26.22 v1(18.47,25.92)
LVDS_TXA_D3N: length 38.8
  TOP w0.114: v1(18.49,30.48) 18.82,30.16 20.21,30.16 20.7,29.67 20.7,28.97 20.89,28.78 21.27,28.78 21.4,28.91 U10.25
  ART03 w0.102: J17.17 30.59,17.2 30.69,17.3 30.69,17.82 30.14,18.37 15.38,18.37 13.79,19.96 13.79,22.45 13.64,22.6 13.64,22.86 13.79,23.01 13.79,23.26 13.64,23.41 13.64,23.67 13.79,23.82 13.79,24.07 13.64,24.23 13.64,24.48 13.79,24.63 13.79,24.89 13.64,25.04 13.64,25.29 13.79,25.45 13.79,25.7 13.64,25.85 13.64,26.11 13.79,26.26 13.79,26.51 13.64,26.67 13.64,26.92 13.79,27.07 13.79,27.33 13.64,27.48 13.64,27.73 13.79,27.88 13.79,28.23 14.62,29.06 15.63,29.06 16.75,30.17 17.36,30.17 17.53,30.35 17.76,30.35 17.94,30.17 18.39,30.17 18.49,30.28 v1(18.49,30.48)
LVDS_TXA_D3P: length 38.9
  TOP w0.114: v1(18.49,29.59) 18.82,29.91 20.11,29.91 20.46,29.57 20.46,28.87 20.79,28.54 21.27,28.54 21.4,28.41 U10.26
  ART03 w0.102: J17.18 29.88,15.91 30.97,17 30.97,17.93 30.26,18.65 15.5,18.65 14.07,20.08 14.07,28.12 14.73,28.78 15.75,28.78 16.87,29.89 18.19,29.89 v1(18.49,29.59)
LVDS_TXB_CLKN: length 11.4
  TOP w0.114: J17.27 20.6,17.2 20.71,17.31 20.71,18.12 21.02,18.43 21.33,18.43 arc(21.45,18.47) 21.49,18.59 arc(21.54,18.7) 21.65,18.74 21.79,18.74 arc(21.9,18.7) 21.95,18.59 arc(22,18.47) 22.11,18.43 22.25,18.43 arc(22.36,18.47) 22.41,18.59 arc(22.45,18.7) 22.56,18.74 22.7,18.74 arc(22.82,18.7) 22.86,18.59 arc(22.91,18.47) 23.02,18.43 23.84,18.43 24.08,18.67 arc(24.12,18.77) 24.08,18.87 arc(24.04,18.97) 24.08,19.07 24.2,19.19 arc(24.3,19.24) 24.4,19.19 arc(24.5,19.15) 24.61,19.19 24.78,19.37 24.78,20.11 arc(24.73,20.22) 24.63,20.26 arc(24.52,20.3) 24.48,20.41 24.48,20.57 arc(24.52,20.67) 24.63,20.72 arc(24.73,20.76) 24.78,20.87 24.78,21.03 arc(24.73,21.13) 24.63,21.17 arc(24.52,21.22) 24.48,21.32 24.48,21.48 arc(24.52,21.59) 24.63,21.63 arc(24.73,21.68) 24.78,21.78 24.78,22.03 24.65,22.16 U10.41
LVDS_TXB_CLKP: length 11.3
  TOP w0.114: U10.42 25.15,22.16 25.02,22.03 25.02,19.27 23.94,18.19 21.12,18.19 20.95,18.02 20.95,16.99 19.88,15.91 J17.28
LVDS_TXB_D0N: length 11.9
  TOP w0.114: J17.19 28.47,17.2 28.71,17.45 28.71,17.69 29.39,18.36 29.72,18.36 29.87,18.52 30.07,18.52 30.23,18.36 30.45,18.36 30.63,18.54 30.63,19.28 arc(30.58,19.4) 30.47,19.44 arc(30.35,19.49) 30.3,19.61 30.3,19.74 arc(30.35,19.85) 30.47,19.9 arc(30.58,19.95) 30.63,20.07 30.63,20.19 arc(30.58,20.31) 30.47,20.36 arc(30.35,20.41) 30.3,20.52 30.3,20.65 arc(30.35,20.77) 30.47,20.82 arc(30.58,20.86) 30.63,20.98 30.63,21.22 30.35,21.5 30.12,21.5 arc(30.01,21.45) 29.96,21.34 arc(29.91,21.21) 29.78,21.16 29.69,21.16 arc(29.56,21.21) 29.5,21.34 arc(29.46,21.45) 29.35,21.5 29.21,21.5 arc(29.09,21.45) 29.05,21.34 arc(28.99,21.21) 28.86,21.16 28.77,21.16 arc(28.64,21.21) 28.59,21.34 arc(28.54,21.45) 28.43,21.5 28.03,21.5 27.78,21.76 27.78,22.03 27.65,22.16 U10.47
LVDS_TXB_D0P: length 12
  TOP w0.114: J17.20 27.88,15.89 28.96,16.97 28.96,17.59 29.49,18.12 30.55,18.12 30.87,18.44 30.87,21.32 30.45,21.74 28.13,21.74 28.02,21.86 28.02,22.03 28.15,22.16 U10.48
LVDS_TXB_D1N: length 12
  TOP w0.114: U10.45 26.65,22.16 26.78,22.03 26.78,21.79 arc(26.73,21.68) 26.63,21.64 arc(26.52,21.6) 26.48,21.49 26.48,21.33 arc(26.52,21.23) 26.63,21.18 arc(26.73,21.14) 26.78,21.03 26.78,20.79 27.13,20.43 27.51,20.43 arc(27.65,20.38) 27.71,20.24 arc(27.77,20.1) 27.91,20.04 27.97,20.04 arc(28.11,20.1) 28.17,20.24 arc(28.22,20.38) 28.36,20.43 29.08,20.43 29.24,20.28 29.24,20.09 29.08,19.94 29.08,19.61 29.24,19.46 29.24,19.24 29.06,19.07 arc(28.97,19.03) 28.87,19.07 arc(28.77,19.11) 28.67,19.07 28.54,18.94 arc(28.5,18.84) 28.54,18.74 arc(28.58,18.65) 28.54,18.55 28.36,18.36 28.15,18.36 arc(28.03,18.42) 27.97,18.54 arc(27.92,18.67) 27.8,18.72 27.7,18.72 arc(27.57,18.67) 27.52,18.54 arc(27.47,18.42) 27.34,18.36 26.98,18.36 26.72,18.11 26.72,17.33 26.59,17.2 J17.21
LVDS_TXB_D1P: length 12
  TOP w0.114: U10.46 27.15,22.16 27.02,22.03 27.02,20.89 27.23,20.67 29.18,20.67 29.48,20.38 29.48,19.14 28.46,18.12 27.08,18.12 26.96,18.01 26.96,16.98 25.88,15.89 J17.22
LVDS_TXB_D2N: length 11
  TOP w0.114: U10.43 25.65,22.16 25.78,22.03 25.78,21.7 arc(25.73,21.59) 25.63,21.55 arc(25.52,21.5) 25.48,21.4 25.48,21.24 arc(25.52,21.13) 25.63,21.09 arc(25.73,21.04) 25.78,20.94 25.78,20.78 arc(25.73,20.67) 25.63,20.63 arc(25.52,20.59) 25.48,20.48 25.48,20.32 arc(25.52,20.22) 25.63,20.17 arc(25.73,20.13) 25.78,20.02 25.78,19.84 26.03,19.58 26.98,19.58 27.11,19.45 27.11,19.26 26.98,19.12 26.46,19.12 26.18,18.84 26.18,18.57 26.07,18.45 25.84,18.45 25.76,18.54 25.76,18.92 25.65,19.02 25.45,19.02 25.35,18.92 25.35,18.57 25.23,18.45 24.97,18.45 24.71,18.2 24.71,17.33 24.59,17.2 J17.23
LVDS_TXB_D2P: length 11.1
  TOP w0.114: U10.44 26.15,22.16 26.02,22.03 26.02,19.94 26.13,19.82 27.08,19.82 27.36,19.55 27.36,19.16 27.08,18.88 26.56,18.88 26.42,18.74 26.42,18.47 26.17,18.21 25.07,18.21 24.96,18.1 24.96,16.95 23.88,15.88 J17.24
LVDS_TXB_D3N: length 11.9
  TOP w0.114: J17.29 18.59,17.2 18.71,17.31 18.71,17.88 18.88,18.05 arc(18.92,18.16) 18.88,18.27 arc(18.83,18.38) 18.88,18.5 18.98,18.6 arc(19.09,18.64) 19.2,18.6 arc(19.31,18.55) 19.42,18.6 19.52,18.7 arc(19.57,18.81) 19.52,18.92 arc(19.48,19.03) 19.52,19.14 19.62,19.24 arc(19.74,19.29) 19.85,19.24 arc(19.96,19.2) 20.07,19.24 20.28,19.46 20.52,19.46 arc(20.65,19.51) 20.7,19.63 arc(20.75,19.76) 20.88,19.81 20.98,19.81 arc(21.11,19.76) 21.16,19.63 arc(21.21,19.51) 21.34,19.46 21.44,19.46 arc(21.56,19.51) 21.62,19.63 arc(21.67,19.76) 21.79,19.81 21.9,19.81 arc(22.02,19.76) 22.07,19.63 arc(22.13,19.51) 22.25,19.46 23.39,19.46 23.78,19.84 23.78,21.03 23.65,21.16 23.65,21.69 23.77,21.82 23.78,21.82 23.78,22.03 23.65,22.16 U10.39
LVDS_TXB_D3P: length 11.9
  TOP w0.114: J17.30 17.88,15.91 18.95,16.99 18.95,17.78 20.38,19.21 23.49,19.21 24.02,19.74 24.02,22.03 24.15,22.16 U10.40
MASKROM: length 4.6
  TOP w0.173: D76.1 30.19,47.34 C165.1 R261.2
  TOP w0.381: D76.1 29.36,47.44 SW1.1
MDIN0_RJ45: length 14.8
  BOTTOM w0.114: 29.14,64.73 28.95,64.92 28.95,68.2 29.06,68.32 ; 29.14,64.73 T2.2 ; 29.14,64.73 28.95,64.53 28.95,64.02 29.29,63.68 T1.2 ; 29.06,68.32 28.95,68.43 28.95,71.7 27.72,72.93 27.72,74.19 27.95,74.42 28.74,74.42 J10.2 ; 29.06,68.32 D10.2
MDIN1_RJ45: length 17.9
  TOP w0.114: v1(30.78,72.77) 30.45,73.09 30.45,73.35 30.64,73.54 32.08,73.54 J10.6
  BOTTOM w0.114: 33.61,64.73 33.39,64.51 33.39,64.02 33.74,63.68 T3.2 ; 33.61,64.73 T4.2 ; 33.61,64.73 33.39,64.94 33.39,68.2 33.51,68.32 ; v1(30.78,72.77) 30.45,72.45 30.45,71.5 30.76,71.2 32.99,71.2 33.39,70.8 33.39,68.43 33.51,68.32 ; 33.51,68.32 D12.2
MDIN2_RJ45: length 19.5
  BOTTOM w0.114: 37.95,68.32 37.84,68.2 37.84,64.86 37.98,64.73 ; 37.95,68.32 D14.2 ; 37.95,68.32 37.84,68.43 37.84,69.23 37.47,69.59 34.76,69.59 34.53,69.82 34.53,72.45 34.09,72.9 32.28,72.9 31.98,73.2 31.98,75.34 J10.5 ; 37.98,64.73 T6.2 ; 37.98,64.73 37.84,64.59 37.84,64.02 38.18,63.68 T5.2
MDIN3_RJ45: length 22.1
  BOTTOM w0.114: D16.2 42.4,68.32 ; 42.4,68.32 42.28,68.43 42.28,70.16 41.91,70.53 35.78,70.53 35.55,70.76 35.55,73.44 35.76,73.66 35.76,74.98 35.53,75.21 35.08,75.21 34.92,75.06 34.92,74.35 J10.8 ; 42.4,68.32 42.28,68.2 42.28,64.89 42.45,64.73 ; 42.45,64.73 42.28,64.57 42.28,64.02 42.63,63.68 T7.2 ; 42.45,64.73 T8.2
MDIP0_RJ45: length 15
  BOTTOM w0.114: J10.1 27.76,75.43 27.76,74.57 27.48,74.29 27.48,72.83 28.71,71.6 28.71,68.43 28.59,68.32 ; 28.46,65.83 28.71,66.08 28.71,68.2 28.59,68.32 ; 28.46,65.83 T2.4 ; 28.46,65.83 28.71,65.58 28.71,64.02 28.37,63.68 T1.3 ; 28.59,68.32 D9.2
MDIP1_RJ45: length 17.6
  TOP w0.114: v1(29.89,72.77) 30.21,73.09 30.21,73.35 30.04,73.53 30.04,73.99 29.82,74.21 29.82,74.45 30.04,74.66 30.04,75.24 J10.3
  BOTTOM w0.114: v1(29.89,72.77) 30.07,72.77 30.21,72.63 30.21,71.4 30.66,70.95 32.89,70.95 33.15,70.7 33.15,68.43 33.04,68.32 ; 33.04,68.32 33.15,68.2 33.15,66.1 32.88,65.83 ; 33.04,68.32 D11.2 ; T3.3 32.81,63.68 33.15,64.02 33.15,65.55 32.88,65.83 ; 32.88,65.83 T4.4
MDIP2_RJ45: length 19.1
  BOTTOM w0.114: D13.2 37.48,68.32 ; 37.48,68.32 37.6,68.2 37.6,66.08 37.35,65.83 ; 37.48,68.32 37.6,68.43 37.6,69.13 37.37,69.35 34.66,69.35 34.29,69.72 34.29,72.35 33.99,72.66 32.18,72.66 31.74,73.1 31.74,74.19 31.58,74.35 J10.4 ; T5.3 37.26,63.68 37.6,64.02 37.6,65.58 37.35,65.83 ; 37.35,65.83 T6.4
MDIP3_RJ45: length 21.9
  BOTTOM w0.114: 41.93,68.32 42.04,68.43 42.04,70.06 41.81,70.29 35.68,70.29 35.31,70.66 35.31,73.4 35.18,73.53 34.16,73.53 33.91,73.79 33.91,75.45 J10.7 ; 41.93,68.32 42.04,68.2 42.04,66.07 41.81,65.84 ; 41.93,68.32 D15.2 ; T8.4 40.67,65.84 41.81,65.84 ; 41.81,65.84 42.04,65.6 42.04,64.02 41.7,63.68 T7.3
MIC1_INN: length 110.8
  TOP w0.254: J3.19 v1(82.86,39.6) ; v1(54.48,76.31) 54.78,76.61 66.39,76.61 67.13,77.36 67.13,77.69 67.13,79.43 67.5,79.8 83.84,79.8 85.07,78.57 87.83,78.57 88.32,79.05 88.32,80.02 88.57,80.28 J4.1
  ART03 w0.254: v1(82.86,39.6) 82.56,39.3 74.75,39.3 74.24,39.81 74.24,58.14 75.21,59.11 75.21,61.9 74.63,62.48 74.63,68.88 75.19,69.45 84.7,69.45 85.39,70.15 85.39,73.91 85.84,74.35 90.06,74.35 90.6,74.9 90.6,77.79 90.6,78.47 90.09,78.98 88.47,78.98 88.21,79.23 88.21,80.02 88.47,80.28 J4.1
  BOTTOM w0.254: v1(54.48,76.31) 54.15,76.64 52.01,76.64 R27.2
MIC1_INP: length 110.3
  TOP w0.254: J3.18 82.96,38.7 v1(82.86,38.6) ; J4.2 87.66,80.28 87.91,80.02 87.91,79.23 87.66,78.98 85.24,78.98 84.01,80.21 67.33,80.21 66.73,79.6 66.73,77.52 66.22,77.02 54.79,77.02 v1(54.48,77.33)
  ART03 w0.254: v1(82.86,38.6) 82.57,38.89 74.54,38.89 73.84,39.6 73.84,58.31 74.8,59.27 74.8,61.73 74.22,62.31 74.22,69.05 75.03,69.86 84.53,69.86 84.99,70.31 84.99,74.07 85.68,74.76 89.89,74.76 90.2,75.07 90.2,78.29 89.92,78.57 88.27,78.57 87.78,79.05 87.78,79.63 J4.2
  BOTTOM w0.254: v1(54.48,77.33) 54.2,77.05 51.96,77.05 R23.2
MIPI_BL_PWM: length 13.7
  BOTTOM w0.173: J18.13 60.18,16.16 60.52,16.51 62.99,16.51 63.99,17.5 70.32,17.5 R184.2
MIPI_CSI_RX0_CLK0N: length 75.5
  TOP w0.114: J3.132 36.94,39.6 37.27,39.93 37.84,39.93 v1(38.16,39.6)
  ART03 w0.102: v1(2.51,17.24) 2.87,17.6 4.26,17.6 8.14,21.48 8.14,36.24 8.95,37.05 8.95,38.67 9.22,38.95 11.17,38.95 11.45,39.23 11.45,40.24 11.57,40.36 11.74,40.36 11.86,40.24 11.86,39.23 12.14,38.95 14.21,38.95 14.49,39.23 14.49,40.24 14.62,40.36 14.79,40.36 14.91,40.25 14.91,39.22 15.18,38.95 15.58,38.95 15.88,39.24 15.88,40.25 16,40.36 16.16,40.36 16.28,40.25 16.28,39.22 16.56,38.95 16.96,38.95 17.25,39.24 17.25,40.25 17.37,40.36 17.54,40.36 17.65,40.25 17.65,39.22 17.93,38.95 18.46,38.95 22.52,43.01 34.67,43.01 35.04,42.64 35.04,40.17 35.3,39.91 37.86,39.91 v1(38.16,39.6)
  BOTTOM w0.114: J24.10 5.75,18.36 5.62,18.49 3.97,18.49 3.82,18.34 3.82,17.91 3.52,17.6 2.88,17.6 v1(2.51,17.24)
MIPI_CSI_RX0_CLK0P: length 75.5
  TOP w0.114: v1(38.16,40.49) 37.84,40.17 37.27,40.17 36.94,40.5 J3.131
  ART03 w0.102: v1(2.51,18.24) 2.87,17.88 4.14,17.88 7.86,21.59 7.86,36.36 8.67,37.17 8.67,38.79 9.11,39.23 11.05,39.23 11.17,39.35 11.17,40.36 11.45,40.64 11.85,40.64 12.14,40.36 12.14,39.35 12.26,39.23 14.1,39.23 14.22,39.35 14.22,40.35 14.51,40.64 14.91,40.64 15.19,40.36 15.19,39.34 15.3,39.23 15.47,39.23 15.6,39.36 15.6,40.36 15.88,40.64 16.28,40.64 16.56,40.36 16.56,39.34 16.67,39.23 16.84,39.23 16.97,39.36 16.97,40.36 17.25,40.64 17.65,40.64 17.93,40.36 17.93,39.34 18.04,39.23 18.34,39.23 22.4,43.29 34.78,43.29 35.32,42.76 35.32,40.29 35.42,40.19 37.86,40.19 v1(38.16,40.49)
  BOTTOM w0.114: J24.9 5.75,18.86 5.62,18.73 3.87,18.73 3.58,18.44 3.58,18.01 3.42,17.84 2.91,17.84 v1(2.51,18.24)
MIPI_CSI_RX0_CLK1N: length 75.3
  TOP w0.114: J3.124 36.94,46.8 37.27,47.13 37.84,47.13 v1(38.16,46.8)
  ART03 w0.102: v1(1.78,32.3) 2.14,32.66 3.26,32.66 3.67,33.07 3.67,44.21 5.61,46.15 15.39,46.15 15.7,46.46 20.27,46.46 20.55,46.74 20.55,47.11 20.67,47.23 20.84,47.23 20.96,47.11 20.96,46.46 21.24,46.18 21.64,46.18 21.92,46.46 21.92,47.11 22.04,47.23 22.21,47.23 22.33,47.11 22.33,46.46 22.61,46.18 23.01,46.18 23.29,46.46 23.29,47.11 23.41,47.23 23.58,47.23 23.7,47.11 23.7,46.46 23.98,46.18 24.38,46.18 24.66,46.46 24.66,47.11 24.78,47.23 24.95,47.23 25.07,47.11 25.07,46.46 25.35,46.18 25.75,46.18 26.04,46.46 26.04,47.11 26.15,47.23 26.32,47.23 26.44,47.11 26.44,46.46 26.72,46.18 27.24,46.18 27.52,46.46 27.52,47.1 27.64,47.22 27.81,47.22 27.92,47.1 27.92,46.46 28.21,46.18 28.61,46.18 28.89,46.46 28.89,47.1 29.01,47.22 29.18,47.22 29.3,47.1 29.3,46.46 29.58,46.18 30.09,46.18 30.37,46.46 30.37,47.12 30.49,47.24 30.66,47.24 30.78,47.12 30.78,46.46 31.06,46.18 32.27,46.18 32.37,46.07 32.37,45.54 32.65,45.27 33.05,45.27 33.34,45.56 33.34,46.01 33.48,46.16 33.64,46.16 33.74,46.05 33.74,45.54 34.02,45.27 34.42,45.27 34.7,45.55 34.7,46.06 34.82,46.18 37.12,46.18 37.39,46.44 37.39,46.95 37.55,47.11 37.86,47.11 v1(38.16,46.8)
  BOTTOM w0.114: v1(1.78,32.3) 2.13,32.65 3.38,32.65 3.75,33.02 3.75,35.65 3.98,35.88 5.62,35.88 5.75,35.75 J28.10
MIPI_CSI_RX0_CLK1P: length 75.3
  TOP w0.114: J3.123 36.94,47.7 37.27,47.37 37.84,47.37 v1(38.16,47.69)
  ART03 w0.102: v1(1.78,33.3) 2.14,32.94 3.15,32.94 3.39,33.19 3.39,44.33 5.5,46.43 15.28,46.43 15.58,46.73 20.15,46.73 20.27,46.85 20.27,47.22 20.55,47.51 20.95,47.51 21.24,47.22 21.24,46.57 21.35,46.46 21.52,46.46 21.64,46.57 21.64,47.22 21.92,47.51 22.32,47.51 22.61,47.22 22.61,46.57 22.73,46.46 22.89,46.46 23.01,46.57 23.01,47.22 23.3,47.51 23.7,47.51 23.98,47.22 23.98,46.57 24.1,46.46 24.27,46.46 24.38,46.57 24.38,47.22 24.67,47.51 25.07,47.51 25.35,47.22 25.35,46.57 25.47,46.46 25.64,46.46 25.76,46.57 25.76,47.22 26.04,47.51 26.44,47.51 26.72,47.22 26.72,46.57 26.84,46.46 27.12,46.46 27.24,46.57 27.24,47.21 27.52,47.5 27.92,47.5 28.2,47.21 28.2,46.57 28.32,46.46 28.49,46.46 28.61,46.57 28.61,47.21 28.89,47.5 29.29,47.5 29.58,47.21 29.58,46.57 29.69,46.46 29.97,46.46 30.09,46.57 30.09,47.24 30.38,47.52 30.78,47.52 31.06,47.24 31.06,46.57 31.18,46.46 32.39,46.46 32.65,46.19 32.65,45.66 32.76,45.55 32.93,45.55 33.06,45.68 33.06,46.13 33.37,46.44 33.76,46.44 34.02,46.17 34.02,45.66 34.13,45.55 34.3,45.55 34.42,45.67 34.42,46.17 34.7,46.46 37.01,46.46 37.11,46.56 37.11,47.07 37.43,47.39 37.86,47.39 v1(38.16,47.69)
  BOTTOM w0.114: v1(1.78,33.3) 2.19,32.89 3.28,32.89 3.51,33.12 3.51,35.75 3.88,36.12 5.62,36.12 5.75,36.25 J28.9
MIPI_CSI_RX0_D0N: length 75.1
  TOP w0.114: v1(38.16,42.3) 37.84,42.63 37.27,42.63 36.94,42.3 J3.129
  ART03 w0.102: v1(2.51,15.24) 2.87,15.6 3.32,15.6 8.84,21.12 8.84,35.74 9.78,36.68 9.78,37.95 10.08,38.25 18.86,38.25 22.42,41.81 25.11,41.81 25.39,41.53 27.1,41.53 27.84,42.26 33.63,42.26 34.17,41.73 34.17,39.06 34.51,38.72 38.67,38.72 39.06,39.1 39.06,41.13 38.65,41.54 37.11,41.54 37.01,41.64 37.01,42.39 37.23,42.61 37.86,42.61 v1(38.16,42.3)
  BOTTOM w0.114: v1(2.51,15.24) 2.9,15.62 4.16,15.62 4.53,15.99 4.53,17.26 4.76,17.49 5.62,17.49 5.75,17.36 J24.12
MIPI_CSI_RX0_D0P: length 75.1
  TOP w0.114: J3.128 36.94,43.2 37.27,42.87 37.84,42.87 v1(38.16,43.19)
  ART03 w0.102: v1(2.51,16.24) 2.87,15.88 3.21,15.88 8.56,21.23 8.56,35.85 9.5,36.79 9.5,38.06 9.97,38.53 18.75,38.53 22.31,42.09 25.22,42.09 25.5,41.81 26.99,41.81 27.72,42.54 33.75,42.54 34.45,41.85 34.45,39.17 34.62,39 38.55,39 38.78,39.22 38.78,41.02 38.53,41.26 37,41.26 36.73,41.52 36.73,42.5 37.12,42.89 37.86,42.89 v1(38.16,43.19)
  BOTTOM w0.114: v1(2.51,16.24) 2.89,15.86 4.06,15.86 4.29,16.09 4.29,17.36 4.66,17.73 5.62,17.73 5.75,17.86 J24.11
MIPI_CSI_RX0_D1N: length 71.9
  TOP w0.114: J3.127 36.94,44.1 37.27,44.43 39.17,44.43 v1(39.5,44.1)
  ART03 w0.102: v1(2.51,19.24) 2.82,19.54 4.78,19.54 5.65,20.42 5.65,25 5.88,25.22 6.78,25.22 7.09,25.53 7.09,25.99 6.79,26.28 5.85,26.28 5.73,26.4 5.73,26.57 5.85,26.69 6.81,26.69 7.09,26.96 7.09,27.36 6.79,27.66 5.85,27.66 5.73,27.77 5.73,27.94 5.85,28.06 6.81,28.06 7.09,28.33 7.09,36.38 8.1,37.4 8.1,41.57 8.33,41.8 14.14,41.8 14.57,41.38 19.89,41.38 22.23,43.71 37.05,43.71 37.75,44.41 39.19,44.41 v1(39.5,44.1)
  BOTTOM w0.114: v1(2.51,19.24) 2.84,19.56 5.54,19.56 5.75,19.36 J24.8
MIPI_CSI_RX0_D1P: length 71.9
  TOP w0.114: v1(39.5,44.99) 39.17,44.67 37.27,44.67 36.94,45 J3.126
  ART03 w0.102: v1(39.5,44.99) 39.19,44.69 37.63,44.69 36.94,43.99 22.11,43.99 19.78,41.65 14.68,41.65 14.25,42.08 8.22,42.08 7.82,41.69 7.82,37.51 6.81,36.5 6.81,28.45 6.7,28.34 5.73,28.34 5.45,28.06 5.45,27.66 5.73,27.38 6.68,27.38 6.81,27.25 6.81,27.08 6.7,26.97 5.73,26.97 5.45,26.69 5.45,26.29 5.73,26 6.68,26 6.81,25.88 6.81,25.65 6.66,25.5 5.76,25.5 5.37,25.11 5.37,20.53 4.67,19.82 2.65,19.82 2.51,19.96 v1(2.51,20.13)
  BOTTOM w0.114: J24.7 5.75,19.86 5.7,19.8 2.84,19.8 v1(2.51,20.13)
MIPI_CSI_RX0_D2N: length 71.3
  TOP w0.114: J3.121 36.94,49.5 37.27,49.83 38.03,49.83 38.16,49.7 v1(38.16,49.5)
  ART03 w0.102: v1(38.16,49.5) 38.16,49.69 38.33,49.86 38.91,49.86 39.17,49.61 39.17,49.35 arc(39.14,49.28) 39.07,49.25 arc(38.99,49.22) 38.96,49.15 38.96,48.94 arc(38.99,48.87) 39.07,48.84 arc(39.14,48.81) 39.17,48.74 39.17,48.54 arc(39.14,48.47) 39.07,48.44 arc(38.99,48.41) 38.96,48.34 38.96,48.13 arc(38.99,48.06) 39.07,48.03 arc(39.14,48) 39.17,47.93 39.17,47.73 arc(39.14,47.65) 39.07,47.62 arc(38.99,47.59) 38.96,47.52 38.96,47.32 arc(38.99,47.25) 39.07,47.22 arc(39.14,47.19) 39.17,47.12 39.17,46.1 38.89,45.82 37.52,45.82 36.52,44.82 31.96,44.82 31.06,45.72 19.15,45.72 19,45.57 17.93,45.57 17.78,45.72 5.88,45.72 4.67,44.51 4.67,44.02 arc(4.64,43.93) 4.54,43.89 arc(4.45,43.86) 4.41,43.76 4.41,43.62 arc(4.45,43.53) 4.54,43.49 arc(4.64,43.45) 4.67,43.36 4.67,43.21 arc(4.64,43.12) 4.54,43.08 arc(4.45,43.04) 4.41,42.95 4.41,42.8 arc(4.45,42.71) 4.54,42.68 arc(4.64,42.64) 4.67,42.55 4.67,42.4 arc(4.64,42.31) 4.54,42.27 arc(4.45,42.23) 4.41,42.14 4.41,41.99 arc(4.45,41.9) 4.54,41.86 arc(4.64,41.82) 4.67,41.73 4.67,40.93 5,40.6 5,37.61 4.24,36.84 4.24,30.17 3.76,29.69 2.24,29.69 2.03,29.91 2.03,30.48 2.2,30.66 2.68,30.66 2.78,30.56 v1(2.78,30.3)
  BOTTOM w0.114: v1(2.78,30.3) 3.16,30.68 3.73,30.68 4.63,31.58 4.63,34.25 5.26,34.88 5.62,34.88 5.75,34.75 J28.12
